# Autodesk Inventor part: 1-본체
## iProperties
Created: 2015-02
Part Number: 1-본체
Material: 알루미늄-6061
Document SubType Name: Modeling
Designer: elite
Mass: 615.363 g
Surface Area: 668.13 cm^2
Volume: 227.071 cm^3
Density: 2.71 g/cm^3
Author: elite
